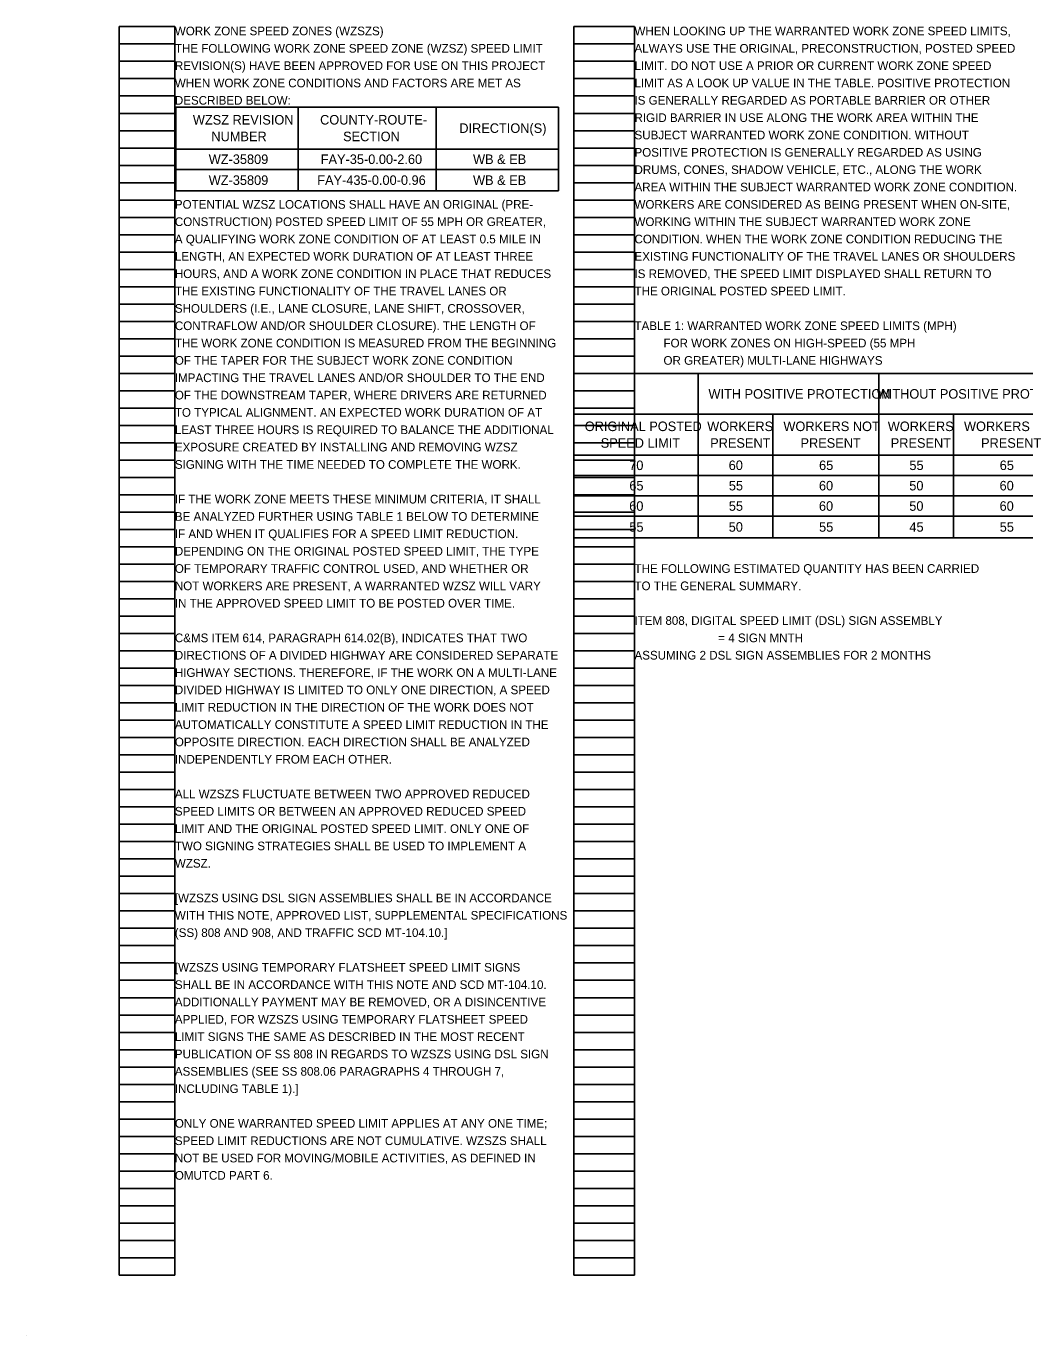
# Model space of a CAD drawing. Extents: x 51924.2 to 51956.2, y 31431.6 to 31530.7.
# Drawn here: x 51924.21 to 51940.33, y 31431.56 to 31452.71 of the extents above; entities that cross this region are included whole.
import ezdxf

# ---------------------------------------------------------------- set-up
doc = ezdxf.new("R2010")
doc.units = 0
doc.layers.add('SH_Data', color=7, linetype='Continuous')
doc.layers.add('SH_Text', color=7, linetype='Continuous')

msp = doc.modelspace()

# ---------------------------------------------------------------- linework, layer by layer
at = {"layer": 'SH_Data'}
for p, q in [((51925.708, 31432.54), (51925.708, 31452.7)), ((51925.708, 31452.7), (51926.608, 31452.7)), ((51926.608, 31432.54), (51926.608, 31452.7)), ((51933.048, 31432.54), (51933.048, 31452.7)), ((51933.048, 31452.7), (51934.028, 31452.7)), ((51934.028, 31432.54), (51934.028, 31452.7)), ((51925.708, 31452.42), (51926.608, 31452.42)), ((51933.048, 31452.42), (51934.028, 31452.42)), ((51925.708, 31452.14), (51926.608, 31452.14)), ((51933.048, 31452.14), (51934.028, 31452.14)), ((51925.708, 31451.86), (51926.608, 31451.86)), ((51933.048, 31451.86), (51934.028, 31451.86)), ((51925.708, 31451.58), (51926.608, 31451.58)), ((51933.048, 31451.58), (51934.028, 31451.58)), ((51925.708, 31451.3), (51926.608, 31451.3)), ((51933.048, 31451.3), (51934.028, 31451.3)), ((51925.708, 31451.02), (51926.608, 31451.02)), ((51933.048, 31451.02), (51934.028, 31451.02)), ((51925.708, 31450.74), (51926.608, 31450.74)), ((51933.048, 31450.74), (51934.028, 31450.74)), ((51925.708, 31450.46), (51926.608, 31450.46)), ((51933.048, 31450.46), (51934.028, 31450.46)), ((51925.708, 31450.18), (51926.608, 31450.18)), ((51933.048, 31450.18), (51934.028, 31450.18)), ((51925.708, 31449.9), (51926.608, 31449.9)), ((51933.048, 31449.9), (51934.028, 31449.9)), ((51925.708, 31449.62), (51926.608, 31449.62)), ((51933.048, 31449.62), (51934.028, 31449.62)), ((51925.708, 31449.34), (51926.608, 31449.34)), ((51933.048, 31449.34), (51934.028, 31449.34)), ((51925.708, 31449.06), (51926.608, 31449.06)), ((51933.048, 31449.06), (51934.028, 31449.06)), ((51925.708, 31448.78), (51926.608, 31448.78)), ((51933.048, 31448.78), (51934.028, 31448.78)), ((51925.708, 31448.5), (51926.608, 31448.5)), ((51933.048, 31448.5), (51934.028, 31448.5)), ((51925.708, 31448.22), (51926.608, 31448.22)), ((51933.048, 31448.22), (51934.028, 31448.22)), ((51925.708, 31447.94), (51926.608, 31447.94)), ((51933.048, 31447.94), (51934.028, 31447.94)), ((51925.708, 31447.66), (51926.608, 31447.66)), ((51933.048, 31447.66), (51934.028, 31447.66)), ((51925.708, 31447.38), (51926.608, 31447.38)), ((51933.048, 31447.38), (51934.028, 31447.38)), ((51925.708, 31447.1), (51926.608, 31447.1)), ((51933.048, 31447.1), (51934.028, 31447.1)), ((51925.708, 31446.82), (51926.608, 31446.82)), ((51933.048, 31446.82), (51934.028, 31446.82)), ((51925.708, 31446.54), (51926.608, 31446.54)), ((51933.048, 31446.54), (51934.028, 31446.54)), ((51925.708, 31446.26), (51926.608, 31446.26)), ((51933.048, 31446.26), (51934.028, 31446.26)), ((51925.708, 31445.98), (51926.608, 31445.98)), ((51933.048, 31445.98), (51934.028, 31445.98)), ((51925.708, 31445.7), (51926.608, 31445.7)), ((51933.048, 31445.7), (51934.028, 31445.7)), ((51925.708, 31445.42), (51926.608, 31445.42)), ((51933.048, 31445.42), (51934.028, 31445.42)), ((51925.708, 31445.14), (51926.608, 31445.14)), ((51933.048, 31445.14), (51934.028, 31445.14)), ((51925.708, 31444.86), (51926.608, 31444.86)), ((51933.048, 31444.86), (51934.028, 31444.86)), ((51925.708, 31444.58), (51926.608, 31444.58)), ((51933.048, 31444.58), (51934.028, 31444.58)), ((51925.708, 31444.3), (51926.608, 31444.3)), ((51933.048, 31444.3), (51934.028, 31444.3)), ((51925.708, 31444.02), (51926.608, 31444.02)), ((51933.048, 31444.02), (51934.028, 31444.02)), ((51925.708, 31443.74), (51926.608, 31443.74)), ((51933.048, 31443.74), (51934.028, 31443.74)), ((51925.708, 31443.46), (51926.608, 31443.46)), ((51933.048, 31443.46), (51934.028, 31443.46)), ((51925.708, 31443.18), (51926.608, 31443.18)), ((51933.048, 31443.18), (51934.028, 31443.18)), ((51925.708, 31442.9), (51926.608, 31442.9)), ((51933.048, 31442.9), (51934.028, 31442.9)), ((51925.708, 31442.62), (51926.608, 31442.62)), ((51933.048, 31442.62), (51934.028, 31442.62)), ((51925.708, 31442.34), (51926.608, 31442.34)), ((51933.048, 31442.34), (51934.028, 31442.34)), ((51925.708, 31442.06), (51926.608, 31442.06)), ((51933.048, 31442.06), (51934.028, 31442.06)), ((51925.708, 31441.78), (51926.608, 31441.78)), ((51933.048, 31441.78), (51934.028, 31441.78)), ((51925.708, 31441.5), (51926.608, 31441.5)), ((51933.048, 31441.5), (51934.028, 31441.5)), ((51925.708, 31441.22), (51926.608, 31441.22)), ((51933.048, 31441.22), (51934.028, 31441.22)), ((51925.708, 31440.94), (51926.608, 31440.94)), ((51933.048, 31440.94), (51934.028, 31440.94)), ((51925.708, 31440.66), (51926.608, 31440.66)), ((51933.048, 31440.66), (51934.028, 31440.66)), ((51925.708, 31440.38), (51926.608, 31440.38)), ((51933.048, 31440.38), (51934.028, 31440.38)), ((51925.708, 31440.1), (51926.608, 31440.1)), ((51933.048, 31440.1), (51934.028, 31440.1)), ((51925.708, 31439.82), (51926.608, 31439.82)), ((51933.048, 31439.82), (51934.028, 31439.82)), ((51925.708, 31439.54), (51926.608, 31439.54)), ((51933.048, 31439.54), (51934.028, 31439.54)), ((51925.708, 31439.26), (51926.608, 31439.26)), ((51933.048, 31439.26), (51934.028, 31439.26)), ((51925.708, 31438.98), (51926.608, 31438.98)), ((51933.048, 31438.98), (51934.028, 31438.98)), ((51925.708, 31438.7), (51926.608, 31438.7)), ((51933.048, 31438.7), (51934.028, 31438.7)), ((51925.708, 31438.42), (51926.608, 31438.42)), ((51933.048, 31438.42), (51934.028, 31438.42)), ((51925.708, 31438.14), (51926.608, 31438.14)), ((51933.048, 31438.14), (51934.028, 31438.14)), ((51925.708, 31437.86), (51926.608, 31437.86)), ((51933.048, 31437.86), (51934.028, 31437.86)), ((51925.708, 31437.58), (51926.608, 31437.58)), ((51933.048, 31437.58), (51934.028, 31437.58)), ((51925.708, 31437.3), (51926.608, 31437.3)), ((51933.048, 31437.3), (51934.028, 31437.3)), ((51925.708, 31437.02), (51926.608, 31437.02)), ((51933.048, 31437.02), (51934.028, 31437.02)), ((51925.708, 31436.74), (51926.608, 31436.74)), ((51933.048, 31436.74), (51934.028, 31436.74)), ((51925.708, 31436.46), (51926.608, 31436.46)), ((51933.048, 31436.46), (51934.028, 31436.46)), ((51925.708, 31436.18), (51926.608, 31436.18)), ((51933.048, 31436.18), (51934.028, 31436.18)), ((51925.708, 31435.9), (51926.608, 31435.9)), ((51933.048, 31435.9), (51934.028, 31435.9)), ((51925.708, 31435.62), (51926.608, 31435.62)), ((51933.048, 31435.62), (51934.028, 31435.62)), ((51925.708, 31435.34), (51926.608, 31435.34)), ((51933.048, 31435.34), (51934.028, 31435.34)), ((51925.708, 31435.06), (51926.608, 31435.06)), ((51933.048, 31435.06), (51934.028, 31435.06)), ((51925.708, 31434.78), (51926.608, 31434.78)), ((51933.048, 31434.78), (51934.028, 31434.78)), ((51925.708, 31434.5), (51926.608, 31434.5)), ((51933.048, 31434.5), (51934.028, 31434.5)), ((51925.708, 31434.22), (51926.608, 31434.22)), ((51933.048, 31434.22), (51934.028, 31434.22)), ((51925.708, 31433.94), (51926.608, 31433.94)), ((51933.048, 31433.94), (51934.028, 31433.94)), ((51925.708, 31433.66), (51926.608, 31433.66)), ((51933.048, 31433.66), (51934.028, 31433.66)), ((51925.708, 31433.38), (51926.608, 31433.38)), ((51933.048, 31433.38), (51934.028, 31433.38)), ((51925.708, 31433.1), (51926.608, 31433.1)), ((51933.048, 31433.1), (51934.028, 31433.1)), ((51925.708, 31432.82), (51926.608, 31432.82)), ((51933.048, 31432.82), (51934.028, 31432.82)), ((51925.708, 31432.54), (51926.608, 31432.54)), ((51933.048, 31432.54), (51934.028, 31432.54)), ((51924.208, 31431.56), (51924.208, 31431.56))]:
    msp.add_line(p, q, dxfattribs=at)
at = {"layer": 'SH_Text'}
for p, q in [((51926.624, 31451.399), (51932.8, 31451.399)), ((51926.624, 31451.399), (51926.624, 31450.049)), ((51928.6, 31451.399), (51928.6, 31450.049)), ((51930.824, 31451.399), (51930.824, 31450.049)), ((51932.8, 31451.399), (51932.8, 31450.049)), ((51926.624, 31450.724), (51932.8, 31450.724)), ((51926.624, 31450.394), (51932.8, 31450.394)), ((51926.624, 31450.049), (51932.8, 31450.049)), ((51933.048, 31447.1), (51940.888, 31447.1)), ((51933.048, 31447.1), (51933.048, 31444.448)), ((51935.058, 31447.1), (51935.058, 31444.448)), ((51937.973, 31447.1), (51937.973, 31444.448)), ((51933.048, 31446.441), (51940.888, 31446.441)), ((51936.26, 31446.441), (51936.26, 31444.448)), ((51939.176, 31446.441), (51939.176, 31444.448)), ((51933.048, 31445.782), (51940.888, 31445.782)), ((51933.048, 31445.453), (51940.888, 31445.453)), ((51933.048, 31445.123), (51940.888, 31445.123)), ((51933.048, 31444.794), (51940.888, 31444.794)), ((51933.048, 31444.448), (51940.888, 31444.448))]:
    msp.add_line(p, q, dxfattribs=at)

# ---------------------------------------------------------------- texts
for s, height, p in [('WORK ZONE SPEED ZONES (WZSZS)', 0.14, (51926.608, 31452.56)), ('WHEN LOOKING UP THE WARRANTED WORK ZONE SPEED LIMITS,', 0.14, (51934.028, 31452.56)), ('THE FOLLOWING WORK ZONE SPEED ZONE (WZSZ) SPEED LIMIT', 0.14, (51926.608, 31452.28)), ('ALWAYS USE THE ORIGINAL, PRECONSTRUCTION, POSTED SPEED', 0.14, (51934.028, 31452.28)), ('REVISION(S) HAVE BEEN APPROVED FOR USE ON THIS PROJECT', 0.14, (51926.608, 31452)), ('LIMIT. DO NOT USE A PRIOR OR CURRENT WORK ZONE SPEED', 0.14, (51934.028, 31452)), ('WHEN WORK ZONE CONDITIONS AND FACTORS ARE MET AS', 0.14, (51926.608, 31451.72)), ('LIMIT AS A LOOK UP VALUE IN THE TABLE. POSITIVE PROTECTION', 0.14, (51934.028, 31451.72)), ('DESCRIBED BELOW:', 0.14, (51926.608, 31451.44)), ('IS GENERALLY REGARDED AS PORTABLE BARRIER OR OTHER', 0.14, (51934.028, 31451.44)), ('WZSZ REVISION ', 0.154, (51926.899, 31451.119)), ('COUNTY-ROUTE-', 0.154, (51928.953, 31451.119)), ('DIRECTION(S)', 0.154, (51931.2, 31450.984)), ('RIGID BARRIER IN USE ALONG THE WORK AREA WITHIN THE', 0.14, (51934.028, 31451.16)), ('NUMBER', 0.154, (51927.198, 31450.85)), ('SECTION', 0.154, (51929.324, 31450.85)), ('SUBJECT WARRANTED WORK ZONE CONDITION. WITHOUT', 0.14, (51934.028, 31450.88)), ('POSITIVE PROTECTION IS GENERALLY REGARDED AS USING', 0.14, (51934.028, 31450.6)), ('WZ-35809', 0.154, (51927.155, 31450.482)), ('FAY-35-0.00-2.60', 0.154, (51928.963, 31450.482)), ('WB & EB', 0.154, (51931.422, 31450.482)), ('WZ-35809', 0.154, (51927.155, 31450.144)), ('FAY-435-0.00-0.96', 0.154, (51928.907, 31450.144)), ('WB & EB', 0.154, (51931.422, 31450.144)), ('DRUMS, CONES, SHADOW VEHICLE, ETC., ALONG THE WORK', 0.14, (51934.028, 31450.32)), ('AREA WITHIN THE SUBJECT WARRANTED WORK ZONE CONDITION.', 0.14, (51934.028, 31450.04)), ('POTENTIAL WZSZ LOCATIONS SHALL HAVE AN ORIGINAL (PRE-', 0.14, (51926.608, 31449.76)), ('WORKERS ARE CONSIDERED AS BEING PRESENT WHEN ON-SITE,', 0.14, (51934.028, 31449.76)), ('CONSTRUCTION) POSTED SPEED LIMIT OF 55 MPH OR GREATER,', 0.14, (51926.608, 31449.48)), ('WORKING WITHIN THE SUBJECT WARRANTED WORK ZONE', 0.14, (51934.028, 31449.48)), ('A QUALIFYING WORK ZONE CONDITION OF AT LEAST 0.5 MILE IN', 0.14, (51926.608, 31449.2)), ('CONDITION. WHEN THE WORK ZONE CONDITION REDUCING THE', 0.14, (51934.028, 31449.2)), ('LENGTH, AN EXPECTED WORK DURATION OF AT LEAST THREE', 0.14, (51926.608, 31448.92)), ('EXISTING FUNCTIONALITY OF THE TRAVEL LANES OR SHOULDERS', 0.14, (51934.028, 31448.92)), ('HOURS, AND A WORK ZONE CONDITION IN PLACE THAT REDUCES', 0.14, (51926.608, 31448.64)), ('IS REMOVED, THE SPEED LIMIT DISPLAYED SHALL RETURN TO', 0.14, (51934.028, 31448.64)), ('THE EXISTING FUNCTIONALITY OF THE TRAVEL LANES OR', 0.14, (51926.608, 31448.36)), ('THE ORIGINAL POSTED SPEED LIMIT.', 0.14, (51934.028, 31448.36)), ('SHOULDERS (I.E., LANE CLOSURE, LANE SHIFT, CROSSOVER,', 0.14, (51926.608, 31448.08)), ('CONTRAFLOW AND/OR SHOULDER CLOSURE). THE LENGTH OF', 0.14, (51926.608, 31447.8)), ('TABLE 1: WARRANTED WORK ZONE SPEED LIMITS (MPH)', 0.14, (51934.028, 31447.8)), ('THE WORK ZONE CONDITION IS MEASURED FROM THE BEGINNING', 0.14, (51926.608, 31447.52)), ('         FOR WORK ZONES ON HIGH-SPEED (55 MPH', 0.14, (51934.028, 31447.52)), ('OF THE TAPER FOR THE SUBJECT WORK ZONE CONDITION', 0.14, (51926.608, 31447.24)), ('         OR GREATER) MULTI-LANE HIGHWAYS', 0.14, (51934.028, 31447.24)), ('IMPACTING THE TRAVEL LANES AND/OR SHOULDER TO THE END', 0.14, (51926.608, 31446.96)), ('OF THE DOWNSTREAM TAPER, WHERE DRIVERS ARE RETURNED', 0.14, (51926.608, 31446.68)), ('WITH POSITIVE PROTECTION', 0.154, (51935.222, 31446.693)), ('WITHOUT POSITIVE PROTECTION', 0.154, (51937.939, 31446.693)), ('TO TYPICAL ALIGNMENT. AN EXPECTED WORK DURATION OF AT', 0.14, (51926.608, 31446.4)), ('LEAST THREE HOURS IS REQUIRED TO BALANCE THE ADDITIONAL', 0.14, (51926.608, 31446.12)), ('ORIGINAL POSTED ', 0.154, (51933.226, 31446.169)), ('WORKERS ', 0.154, (51935.202, 31446.169)), ('WORKERS NOT ', 0.154, (51936.432, 31446.169)), ('WORKERS ', 0.154, (51938.117, 31446.169)), ('WORKERS NOT ', 0.154, (51939.347, 31446.169)), ('SPEED LIMIT', 0.154, (51933.483, 31445.9)), ('PRESENT', 0.154, (51935.25, 31445.9)), ('PRESENT', 0.154, (51936.708, 31445.9)), ('PRESENT', 0.154, (51938.165, 31445.9)), ('PRESENT', 0.154, (51939.623, 31445.9)), ('EXPOSURE CREATED BY INSTALLING AND REMOVING WZSZ', 0.14, (51926.608, 31445.84)), ('SIGNING WITH THE TIME NEEDED TO COMPLETE THE WORK.', 0.14, (51926.608, 31445.56)), ('70', 0.154, (51933.943, 31445.54)), ('60', 0.154, (51935.549, 31445.54)), ('65', 0.154, (51937.008, 31445.54)), ('55', 0.154, (51938.466, 31445.54)), ('65', 0.154, (51939.924, 31445.54)), ('65', 0.154, (51933.945, 31445.211)), ('55', 0.154, (51935.551, 31445.211)), ('60', 0.154, (51937.006, 31445.211)), ('50', 0.154, (51938.464, 31445.211)), ('60', 0.154, (51939.922, 31445.211)), ('IF THE WORK ZONE MEETS THESE MINIMUM CRITERIA, IT SHALL', 0.14, (51926.608, 31445)), ('60', 0.154, (51933.943, 31444.882)), ('55', 0.154, (51935.551, 31444.882)), ('60', 0.154, (51937.006, 31444.882)), ('50', 0.154, (51938.464, 31444.882)), ('60', 0.154, (51939.922, 31444.882)), ('BE ANALYZED FURTHER USING TABLE 1 BELOW TO DETERMINE', 0.14, (51926.608, 31444.72)), ('IF AND WHEN IT QUALIFIES FOR A SPEED LIMIT REDUCTION.', 0.14, (51926.608, 31444.44)), ('55', 0.154, (51933.945, 31444.544)), ('50', 0.154, (51935.549, 31444.544)), ('55', 0.154, (51937.008, 31444.544)), ('45', 0.154, (51938.466, 31444.544)), ('55', 0.154, (51939.924, 31444.544)), ('DEPENDING ON THE ORIGINAL POSTED SPEED LIMIT, THE TYPE', 0.14, (51926.608, 31444.16)), ('OF TEMPORARY TRAFFIC CONTROL USED, AND WHETHER OR', 0.14, (51926.608, 31443.88)), ('THE FOLLOWING ESTIMATED QUANTITY HAS BEEN CARRIED', 0.14, (51934.028, 31443.88)), ('NOT WORKERS ARE PRESENT, A WARRANTED WZSZ WILL VARY', 0.14, (51926.608, 31443.6)), ('TO THE GENERAL SUMMARY.', 0.14, (51934.028, 31443.6)), ('IN THE APPROVED SPEED LIMIT TO BE POSTED OVER TIME.', 0.14, (51926.608, 31443.32)), ('ITEM 808, DIGITAL SPEED LIMIT (DSL) SIGN ASSEMBLY', 0.14, (51934.028, 31443.04)), ('C&MS ITEM 614, PARAGRAPH 614.02(B), INDICATES THAT TWO', 0.14, (51926.608, 31442.76)), ('                          = 4 SIGN MNTH', 0.14, (51934.028, 31442.76)), ('DIRECTIONS OF A DIVIDED HIGHWAY ARE CONSIDERED SEPARATE', 0.14, (51926.608, 31442.48)), ('ASSUMING 2 DSL SIGN ASSEMBLIES FOR 2 MONTHS', 0.14, (51934.028, 31442.48)), ('HIGHWAY SECTIONS. THEREFORE, IF THE WORK ON A MULTI-LANE', 0.14, (51926.608, 31442.2)), ('DIVIDED HIGHWAY IS LIMITED TO ONLY ONE DIRECTION, A SPEED', 0.14, (51926.608, 31441.92)), ('LIMIT REDUCTION IN THE DIRECTION OF THE WORK DOES NOT', 0.14, (51926.608, 31441.64)), ('AUTOMATICALLY CONSTITUTE A SPEED LIMIT REDUCTION IN THE', 0.14, (51926.608, 31441.36)), ('OPPOSITE DIRECTION. EACH DIRECTION SHALL BE ANALYZED', 0.14, (51926.608, 31441.08)), ('INDEPENDENTLY FROM EACH OTHER.', 0.14, (51926.608, 31440.8)), ('ALL WZSZS FLUCTUATE BETWEEN TWO APPROVED REDUCED', 0.14, (51926.608, 31440.24)), ('SPEED LIMITS OR BETWEEN AN APPROVED REDUCED SPEED', 0.14, (51926.608, 31439.96)), ('LIMIT AND THE ORIGINAL POSTED SPEED LIMIT. ONLY ONE OF', 0.14, (51926.608, 31439.68)), ('TWO SIGNING STRATEGIES SHALL BE USED TO IMPLEMENT A', 0.14, (51926.608, 31439.4)), ('WZSZ.', 0.14, (51926.608, 31439.12)), ('[WZSZS USING DSL SIGN ASSEMBLIES SHALL BE IN ACCORDANCE', 0.14, (51926.608, 31438.56)), ('WITH THIS NOTE, APPROVED LIST, SUPPLEMENTAL SPECIFICATIONS', 0.14, (51926.608, 31438.28)), ('(SS) 808 AND 908, AND TRAFFIC SCD MT-104.10.]', 0.14, (51926.608, 31438)), ('[WZSZS USING TEMPORARY FLATSHEET SPEED LIMIT SIGNS', 0.14, (51926.608, 31437.44)), ('SHALL BE IN ACCORDANCE WITH THIS NOTE AND SCD MT-104.10.', 0.14, (51926.608, 31437.16)), ('ADDITIONALLY PAYMENT MAY BE REMOVED, OR A DISINCENTIVE', 0.14, (51926.608, 31436.88)), ('APPLIED, FOR WZSZS USING TEMPORARY FLATSHEET SPEED', 0.14, (51926.608, 31436.6)), ('LIMIT SIGNS THE SAME AS DESCRIBED IN THE MOST RECENT', 0.14, (51926.608, 31436.32)), ('PUBLICATION OF SS 808 IN REGARDS TO WZSZS USING DSL SIGN', 0.14, (51926.608, 31436.04)), ('ASSEMBLIES (SEE SS 808.06 PARAGRAPHS 4 THROUGH 7,', 0.14, (51926.608, 31435.76)), ('INCLUDING TABLE 1).]', 0.14, (51926.608, 31435.48)), ('ONLY ONE WARRANTED SPEED LIMIT APPLIES AT ANY ONE TIME;', 0.14, (51926.608, 31434.92)), ('SPEED LIMIT REDUCTIONS ARE NOT CUMULATIVE. WZSZS SHALL', 0.14, (51926.608, 31434.64)), ('NOT BE USED FOR MOVING/MOBILE ACTIVITIES, AS DEFINED IN', 0.14, (51926.608, 31434.36)), ('OMUTCD PART 6.', 0.14, (51926.608, 31434.08))]:
    msp.add_text(s, height=height, dxfattribs=at).set_placement(p)

doc.saveas('drawing.dxf')
